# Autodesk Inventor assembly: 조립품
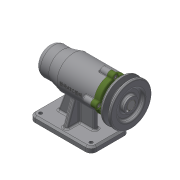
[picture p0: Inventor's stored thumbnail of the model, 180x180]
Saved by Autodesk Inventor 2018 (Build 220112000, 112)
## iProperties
Created: 2019-07
Part Number: 조립품
Material: 일반
Document SubType Name: Assembly
Designer: USER
Author: USER
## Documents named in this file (11)
- C:\Users\USER\Desktop\490704V1068\조립품.iam
- C:\Users\USER\Desktop\490704V1068\본체.ipt
- C:\Users\USER\Desktop\490704V1068\베어링 51202.ipt
- C:\Users\USER\Desktop\490704V1068\축.ipt
- C:\Users\USER\Desktop\490704V1068\베어링 6004.ipt
- C:\Users\USER\Desktop\490704V1068\어댑터슬리브.ipt
- C:\Users\USER\Desktop\490704V1068\볼트 M4.ipt
- C:\Users\USER\Desktop\490704V1068\V벨트풀리.ipt
- C:\Users\USER\Desktop\490704V1068\키 5 x 5 x 16.ipt
- C:\Users\USER\Desktop\490704V1068\멈춤나사 M3.ipt
- C:\Users\USER\Desktop\490704V1068\커버.ipt
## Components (1 placed, 1 different names)
1. V벨트풀리:1
